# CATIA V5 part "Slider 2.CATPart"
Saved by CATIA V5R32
Part number: Part 3
Bounding box of the stored display mesh (mm): x 0 to 20, y -5 to 5, z -5 to 5
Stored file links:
  D:\PROJECTS\Project 2022\CATIA V5 6R 2022\Resources\Part Files\c16_catia_v5_6r2022_prt\Cable Joint - (Fig16-60)\Slider 2.CATPart
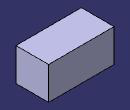
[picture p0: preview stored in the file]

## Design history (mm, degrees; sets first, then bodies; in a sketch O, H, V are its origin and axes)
Body1 (main body)
  Sketch1 on yz-plane, origin (0, 0, 0), H (0, 1, 0), V (0, 0, 1)
    line L1 (5, 5) -> (5, -5)
    line L2 (5, -5) -> (-5, -5)
    line L3 (-5, -5) -> (-5, 5)
    line L4 (-5, 5) -> (5, 5)
    length L4 = 10
    length L1 = 10
    vertical: L1 V, L3 V
    horizontal: L2 H, L4 H
    equidistance: L1 L3 O, L2 L4 O
  Pad1: profile Sketch1, direction (1, 0, 0), length 20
